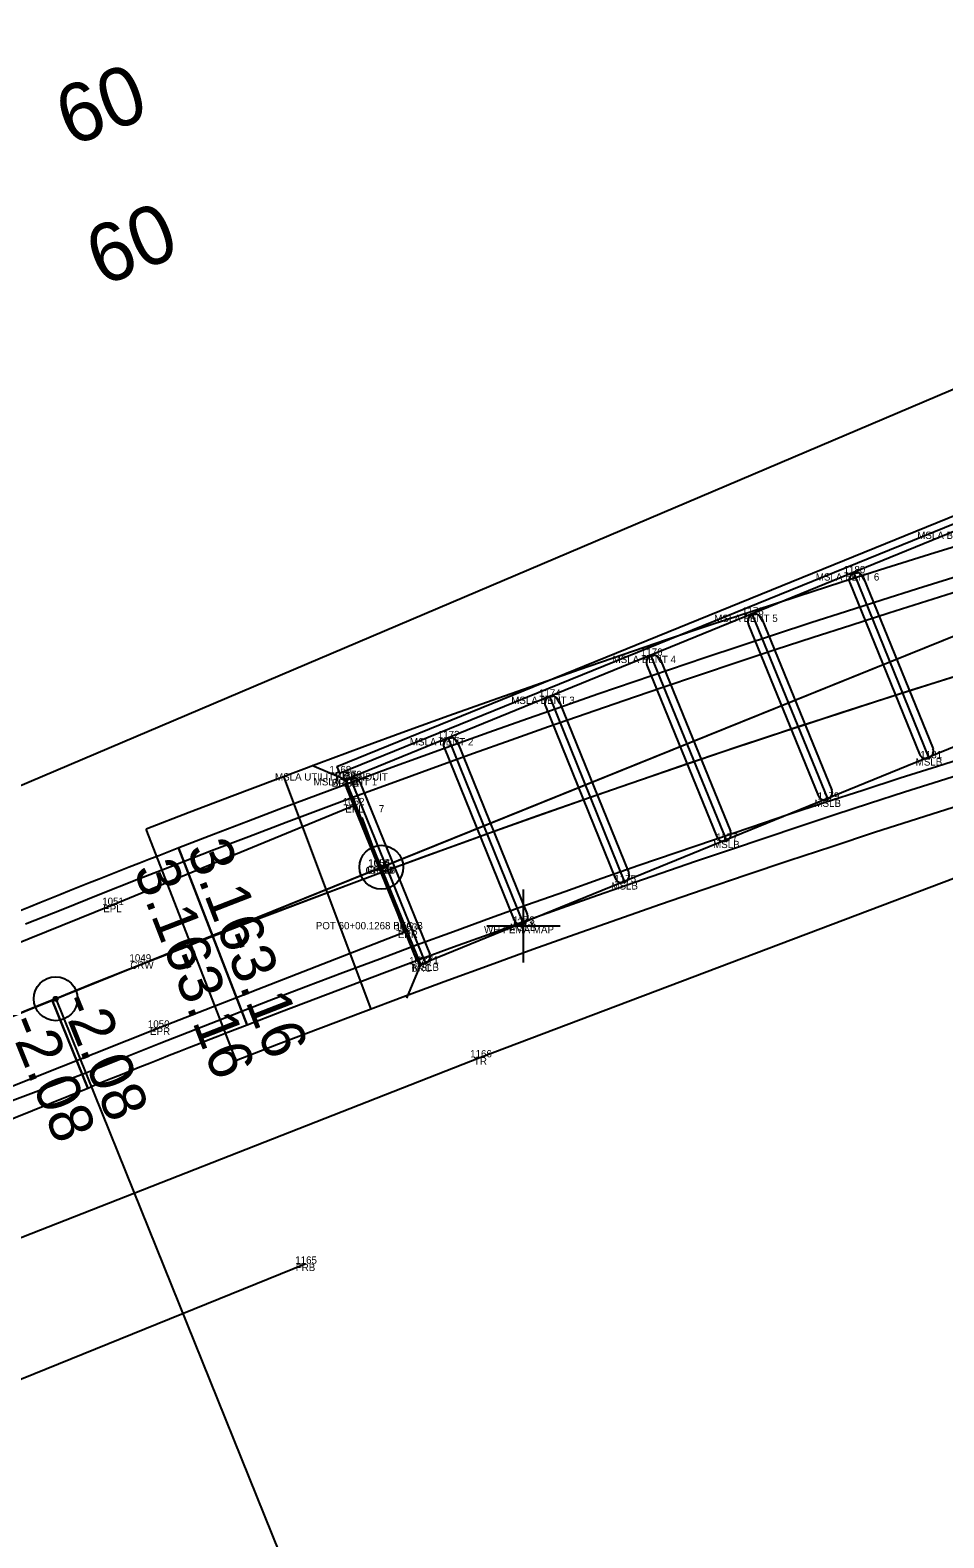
# Model space of a CAD drawing. Extents: x 1965498 to 1971309, y 1116335 to 1119906.
# Drawn here: x 1967650 to 1967775.1, y 1117730.9 to 1117937.3 of the extents above; entities that cross this region are included whole.
import ezdxf

# ---------------------------------------------------------------- set-up
doc = ezdxf.new("R2010")
doc.units = 0
for name, color, linetype in [('Level 1', 7, 'Continuous'), ('Level 11', 7, 'Continuous'), ('Level 12', 7, 'Continuous'), ('Level 15', 7, 'Continuous'), ('Level 19', 7, 'Continuous'), ('Level 2', 7, 'Continuous'), ('Level 20', 7, 'Continuous'), ('Level 21', 7, 'Continuous'), ('Level 3', 7, 'Continuous'), ('Level 39', 7, 'Continuous'), ('Level 5', 7, 'Continuous'), ('Level 50', 7, 'Continuous'), ('Level 51', 7, 'Continuous'), ('Level 52', 7, 'Continuous'), ('Level 53', 7, 'Continuous'), ('Level 55', 7, 'Continuous'), ('Level 58', 7, 'Continuous'), ('Level 60', 7, 'Continuous'), ('Level 61', 7, 'Continuous'), ('Level 63', 7, 'Continuous'), ('Level 8', 7, 'Continuous'), ('Level 9', 7, 'Continuous')]:
    doc.layers.add(name, color=color, linetype=linetype)

msp = doc.modelspace()

# ---------------------------------------------------------------- linework, layer by layer
at = {"layer": 'Level 1'}
for p, q in [((1966770.74, 1117448.12), (1967849.47, 1117883.86)), ((1967697.95, 1117822.66), (1967694.95, 1117830.07)), ((1967697.95, 1117822.66), (1967700.95, 1117815.24))]:
    msp.add_line(p, q, dxfattribs=at)
for radius in [3, 0.282]:
    msp.add_circle((1967698.07, 1117822.7), radius, dxfattribs=at)
at = {"layer": 'Level 11'}
for points in [[(1967422.03, 1117809.72), (1967453.38, 1117748.92), (1967559.8, 1117796.17), (1967844.47, 1117917.07), (1967917.86, 1117947.25), (1968009.67, 1117958.84), (1968061.48, 1117958.08), (1968105.8, 1117963.33), (1968158.86, 1117956.79), (1968212.37, 1117954.08), (1968423.16, 1117946.63), (1968536.42, 1117942.26)], [(1967303.54, 1117601.01), (1967338.99, 1117640.22), (1967353.28, 1117654.56), (1967394.76, 1117667.24), (1967484.61, 1117707.66), (1967711.58, 1117796.67), (1967890.09, 1117864.21), (1967929.29, 1117872.68), (1967959.15, 1117877.99), (1967976.93, 1117884.5), (1968014.32, 1117894.35), (1968104.14, 1117889.87), (1968155.31, 1117895.48), (1968209.85, 1117895.88), (1968320.55, 1117893.51), (1968423.04, 1117892.22), (1968529.15, 1117876.96)]]:
    msp.add_lwpolyline(points, dxfattribs=at)
at = {"layer": 'Level 12'}
for p, q in [((1967698.07, 1117822.7), (1967825.19, 1117874.05)), ((1966770.74, 1117448.12), (1967698.07, 1117822.7))]:
    msp.add_line(p, q, dxfattribs=at)
at = {"layer": 'Level 15'}
for p, q in [((1967696.7, 1117803.29), (1967684.74, 1117835.12)), ((1967678.21, 1117796.22), (1967665.86, 1117827.9))]:
    msp.add_line(p, q, dxfattribs=at)
for radius in [1654.02, 1620.02]:
    msp.add_arc((1968266.61, 1116286.83), radius, 97.29689, 111.29689, dxfattribs=at)
at = {"layer": 'Level 19'}
for p, q in [((1967698.21, 1117822), (1967695.43, 1117829.51)), ((1967698.21, 1117822), (1967700.99, 1117814.5)), ((1967512.51, 1117747.75), (1967653.48, 1117804.69))]:
    msp.add_line(p, q, dxfattribs=at)
for radius in [3, 0.282]:
    msp.add_circle((1967653.48, 1117804.69), radius, dxfattribs=at)
msp.add_arc((1968266.61, 1116286.83), 1637.02, 87.72663, 111.99584, dxfattribs=at)
at = {"layer": 'Level 2'}
for p, q in [((1967762.76, 1117862.95), (1967773.06, 1117837.62)), ((1967764.06, 1117862.4), (1967773.61, 1117838.93)), ((1967762.21, 1117861.65), (1967771.76, 1117838.17)), ((1967748.32, 1117855.97), (1967757.89, 1117832.51)), ((1967748.87, 1117857.28), (1967759.19, 1117831.96)), ((1967750.17, 1117856.73), (1967759.74, 1117833.26)), ((1967734.98, 1117851.66), (1967745.32, 1117826.32)), ((1967734.43, 1117850.35), (1967744.02, 1117826.87)), ((1967736.29, 1117851.11), (1967745.87, 1117827.62)), ((1967721.09, 1117846.06), (1967731.39, 1117820.65)), ((1967722.39, 1117845.51), (1967731.94, 1117821.95)), ((1967720.54, 1117844.76), (1967730.09, 1117821.2)), ((1967706.66, 1117839.07), (1967716.2, 1117815.53)), ((1967707.21, 1117840.37), (1967717.5, 1117814.98)), ((1967708.51, 1117839.82), (1967718.05, 1117816.28)), ((1967693.82, 1117834.9), (1967704.14, 1117809.51)), ((1967693.27, 1117833.6), (1967702.83, 1117810.06)), ((1967695.12, 1117834.35), (1967704.69, 1117810.82))]:
    msp.add_line(p, q, dxfattribs=at)
for centre, start, end in [((1967763.13, 1117862.02), 22.1353, 202.1353), ((1967749.25, 1117856.35), 22.1792, 202.1792), ((1967735.36, 1117850.73), 22.2033, 202.2033), ((1967721.46, 1117845.13), 22.0712, 202.0712), ((1967707.58, 1117839.44), 22.0738, 202.0738), ((1967772.68, 1117838.55), 202.1353, 22.1353), ((1967694.2, 1117833.98), 22.1192, 202.1192), ((1967758.81, 1117832.89), 202.1792, 22.1792), ((1967744.95, 1117827.25), 202.2033, 22.2033), ((1967731.01, 1117821.58), 202.0712, 22.0712), ((1967717.13, 1117815.91), 202.0738, 22.0738), ((1967703.76, 1117810.44), 202.1192, 22.1192)]:
    msp.add_arc(centre, 1, start, end, dxfattribs=at)
at = {"layer": 'Level 20'}
msp.add_line((1967657.6, 1117794.49), (1967563.88, 1117759.49), dxfattribs=at)
for radius in [1648.02, 1626.02]:
    msp.add_arc((1968266.61, 1116286.83), radius, 87.72663, 111.99584, dxfattribs=at)
at = {"layer": 'Level 3'}
for p, q in [((1967661.25, 1117817.53), (1967694.4, 1117831.19)), ((1967566.67, 1117779.5), (1967661.25, 1117817.53)), ((1967667.7, 1117800.74), (1967701.64, 1117814)), ((1967573.92, 1117763.51), (1967667.7, 1117800.74))]:
    msp.add_line(p, q, dxfattribs=at)
at = {"layer": 'Level 39'}
msp.add_line((1967653.48, 1117804.69), (1967714.92, 1117652.58), dxfattribs=at)
at = {"layer": 'Level 5'}
for p, q in [((1967688.55, 1117836.67), (1967693.16, 1117834.73)), ((1967701.56, 1117804.79), (1967703.5, 1117809.4))]:
    msp.add_line(p, q, dxfattribs=at)
msp.add_lwpolyline([(1967693.16, 1117834.73), (1967873.65, 1117908.38), (1967883.99, 1117883.05), (1967703.5, 1117809.4), (1967693.16, 1117834.73)], dxfattribs=at)
at = {"layer": 'Level 50'}
for centre in [(1967762.76, 1117862.95), (1967748.87, 1117857.28), (1967734.98, 1117851.66), (1967721.09, 1117846.06), (1967707.21, 1117840.37), (1967773.06, 1117837.62), (1967692.35, 1117835.57), (1967693.82, 1117834.9), (1967693.16, 1117834.73), (1967693.16, 1117834.73), (1967694.4, 1117831.19), (1967759.19, 1117831.96), (1967745.32, 1117826.32), (1967697.89, 1117822.8), (1967697.89, 1117822.8), (1967697.89, 1117822.8), (1967698.07, 1117822.7), (1967731.39, 1117820.65), (1967661.25, 1117817.53), (1967717.5, 1117814.98), (1967701.64, 1117814), (1967665.19, 1117809.79), (1967703.5, 1117809.4), (1967704.14, 1117809.51), (1967667.7, 1117800.74), (1967711.58, 1117796.67), (1967687.66, 1117768.42)]:
    msp.add_circle(centre, 0.001, dxfattribs=at)
at = {"layer": 'Level 52'}
for p, q in [((1967717.54, 1117809.67), (1967717.54, 1117819.67)), ((1967712.54, 1117814.67), (1967722.54, 1117814.67))]:
    msp.add_line(p, q, dxfattribs=at)
msp.add_circle((1967717.54, 1117814.67), 0.001, dxfattribs=at)
at = {"layer": 'Level 63'}
for p, q in [((1967670.32, 1117825.34), (1967675.02, 1117813.22)), ((1967675.02, 1117813.22), (1967670.32, 1117825.34)), ((1967679.71, 1117801.09), (1967675.02, 1117813.22)), ((1967675.02, 1117813.22), (1967679.71, 1117801.09)), ((1967653, 1117804.5), (1967327.07, 1117672.84)), ((1967653.48, 1117804.69), (1967568, 1117770.16)), ((1967653.48, 1117804.69), (1967653, 1117804.5)), ((1967657.87, 1117792.44), (1967653, 1117804.5)), ((1967653, 1117804.5), (1967657.87, 1117792.44)), ((1967331.94, 1117660.79), (1967657.87, 1117792.44)), ((1967657.87, 1117792.44), (1967658.35, 1117792.64))]:
    msp.add_line(p, q, dxfattribs=at)
for radius, start, end in [(1650.02, 88.53761, 111.18506), (1637.02, 88.53761, 111.18506), (1637.02, 88.53761, 111.18506), (1624.02, 88.53761, 111.18506), (1650.02, 111.18506, 111.99584), (1637.02, 111.18506, 111.99584), (1637.02, 111.18506, 111.99584), (1624.02, 111.18506, 111.99584)]:
    msp.add_arc((1968266.61, 1116286.83), radius, start, end, dxfattribs=at)
at = {"layer": 'Level 8'}
msp.add_lwpolyline([(1967532.54, 1117707.33), (1967583.14, 1117726.03), (1967687.66, 1117768.42)], dxfattribs=at)
at = {"layer": 'Level 9'}
for p, q in [((1967691.97, 1117836.5), (1967874.09, 1117910.51)), ((1967692.35, 1117835.57), (1967874.47, 1117909.58)), ((1967691.97, 1117836.5), (1967692.35, 1117835.57))]:
    msp.add_line(p, q, dxfattribs=at)

# ---------------------------------------------------------------- texts
at = {"layer": 'Level 19'}
msp.add_text('60', height=8, rotation=20.3169, dxfattribs=at).set_placement((1967655.44, 1117921.33))
at = {"layer": 'Level 21'}
msp.add_text('60', height=8, rotation=21.9958, dxfattribs=at).set_placement((1967659.78, 1117902.15))
at = {"layer": 'Level 51'}
for s, p in [('7', (1967697.73, 1117830.2)), ('POT 60+00.1268 BEG.B', (1967689.1, 1117814.2))]:
    msp.add_text(s, height=1, dxfattribs=at).set_placement(p)
at = {"layer": 'Level 52'}
for s, p in [('MSLA BENT 7', (1967771.45, 1117867.65)), ('1180', (1967761.36, 1117862.95)), ('MSLA BENT 6', (1967757.56, 1117861.95)), ('1178', (1967747.46, 1117857.28)), ('MSLA BENT 5', (1967743.65, 1117856.28)), ('MSLA BENT 4', (1967729.73, 1117850.66)), ('1176', (1967733.6, 1117851.66)), ('MSLA BENT 3', (1967715.86, 1117845.06)), ('1174', (1967719.66, 1117846.06)), ('1172', (1967705.8, 1117840.37)), ('MSLA BENT 2', (1967701.98, 1117839.37)), ('MSLB', (1967771.24, 1117836.62)), ('1181', (1967771.88, 1117837.62)), ('MSLA UTILITY CONDUIT', (1967683.51, 1117834.57)), ('MSLA BENT 1', (1967688.81, 1117833.9)), ('1168', (1967690.97, 1117835.57)), ('1170', (1967692.42, 1117834.9)), ('1179', (1967757.81, 1117831.96)), ('MSLB', (1967757.37, 1117830.96)), ('1177', (1967743.91, 1117826.32)), ('MSLB', (1967743.5, 1117825.32)), ('MSLB', (1967729.57, 1117819.65)), ('1175', (1967729.98, 1117820.65)), ('MSLB', (1967715.68, 1117813.98)), ('1173', (1967716.1, 1117814.98)), ('1171', (1967702.95, 1117809.51)), ('MSLB', (1967702.32, 1117808.51))]:
    msp.add_text(s, height=1, dxfattribs=at).set_placement(p)
at = {"layer": 'Level 53'}
for s, p in [('1052', (1967692.79, 1117831.19)), ('EPL', (1967693.14, 1117830.19)), ('CRWB', (1967695.9, 1117821.8)), ('EPRB', (1967696.09, 1117821.8)), ('EPLB', (1967696.14, 1117821.8)), ('1054', (1967696.26, 1117822.8)), ('1055', (1967696.28, 1117822.8)), ('1056', (1967696.31, 1117822.8)), ('1051', (1967659.85, 1117817.53)), ('EPL', (1967659.99, 1117816.53)), ('1053', (1967700.03, 1117814)), ('EPR', (1967700.33, 1117813)), ('1049', (1967663.58, 1117809.79)), ('CRW', (1967663.7, 1117808.79)), ('1050', (1967666.1, 1117800.74)), ('EPR', (1967666.4, 1117799.74))]:
    msp.add_text(s, height=1, dxfattribs=at).set_placement(p)
at = {"layer": 'Level 55'}
for s, p in [('1073', (1967691.54, 1117834.73)), ('1069', (1967691.6, 1117834.73)), ('BRCA', (1967691.26, 1117833.73)), ('BRCB', (1967691.31, 1117833.73)), ('1072', (1967701.88, 1117809.4)), ('BRC', (1967702.15, 1117808.4))]:
    msp.add_text(s, height=1, dxfattribs=at).set_placement(p)
at = {"layer": 'Level 58'}
for s, p in [('1165', (1967686.28, 1117768.42)), ('FRB', (1967686.35, 1117767.42))]:
    msp.add_text(s, height=1, dxfattribs=at).set_placement(p)
at = {"layer": 'Level 60'}
msp.add_text('WH FEMA MAP', height=1, dxfattribs=at).set_placement((1967712.13, 1117813.67))
at = {"layer": 'Level 61'}
for s, p in [('1273', (1967715.92, 1117814.67)), ('1166', (1967710.23, 1117796.67)), ('TR', (1967710.75, 1117795.67))]:
    msp.add_text(s, height=1, dxfattribs=at).set_placement(p)
at = {"layer": 'Level 63'}
for s, rotation, p in [('3.16', 291.1851, (1967671.36, 1117825.18)), ('3.16', 291.1851, (1967664.08, 1117822.36)), ('-3.16', 291.1851, (1967676.05, 1117813.06)), ('-3.16', 291.1851, (1967668.78, 1117810.24)), ('-2.08', 291.9958, (1967654.04, 1117804.36)), ('-2.08', 291.9958, (1967646.81, 1117801.44))]:
    msp.add_text(s, height=5.98, rotation=rotation, dxfattribs=at).set_placement(p)

doc.saveas('drawing.dxf')
